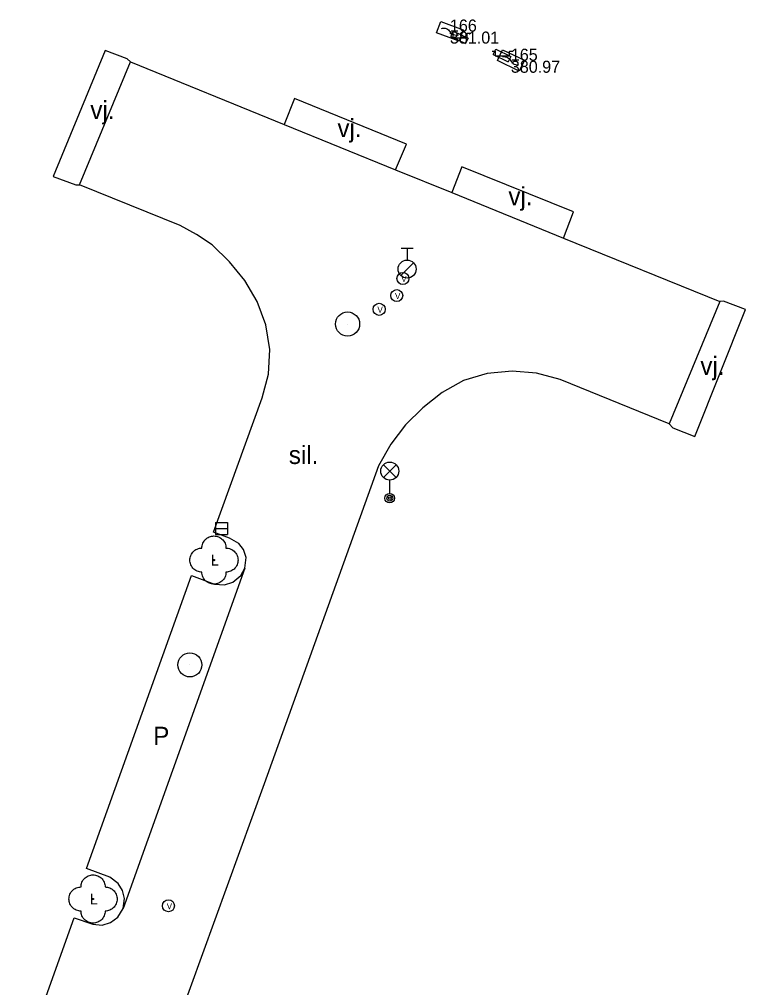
# Model space of a CAD drawing. Extents: x -836568 to -836015, y -1070547 to -1070212.
# Drawn here: x -836294.58 to -836264.42, y -1070423.41 to -1070383.21 of the extents above; entities that cross this region are included whole.
import ezdxf

# ---------------------------------------------------------------- set-up
doc = ezdxf.new("R2010")
doc.units = 0
for name, color, linetype in [('BodPole_mer', 7, 'Continuous'), ('BodPole_popis', 7, 'Continuous'), ('Doprava_hranice', 7, 'Continuous'), ('Doprava_kody', 7, 'Continuous'), ('PovrZnIS_body', 7, 'Continuous'), ('PovrZnIS_hranice', 7, 'Continuous'), ('PovrZnIS_kody', 7, 'Continuous'), ('Zelen_body', 7, 'Continuous')]:
    doc.layers.add(name, color=color, linetype=linetype)

msp = doc.modelspace()

# ---------------------------------------------------------------- linework, layer by layer
at = {"layer": 'BodPole_mer'}
for p, q in [((-836276.7, -1070383.72), (-836276.7, -1070383.72)), ((-836276.66, -1070383.93), (-836276.66, -1070383.93)), ((-836276.66, -1070383.93), (-836276.66, -1070383.93)), ((-836276.55, -1070383.7), (-836276.55, -1070383.7)), ((-836276.55, -1070383.7), (-836276.55, -1070383.7)), ((-836275.94, -1070383.99), (-836275.94, -1070383.99)), ((-836275.94, -1070383.99), (-836275.94, -1070383.99)), ((-836291.02, -1070384.5), (-836291.02, -1070384.5)), ((-836276.05, -1070384.22), (-836276.05, -1070384.22)), ((-836276.05, -1070384.22), (-836276.05, -1070384.22)), ((-836274.79, -1070384.45), (-836274.79, -1070384.45)), ((-836274.79, -1070384.45), (-836274.79, -1070384.45)), ((-836290.1, -1070384.85), (-836290.1, -1070384.85)), ((-836274.9, -1070384.67), (-836274.9, -1070384.67)), ((-836274.9, -1070384.67), (-836274.9, -1070384.67)), ((-836274.17, -1070384.76), (-836274.17, -1070384.76)), ((-836274.17, -1070384.76), (-836274.17, -1070384.76)), ((-836289.97, -1070384.98), (-836289.97, -1070384.98)), ((-836274.28, -1070384.98), (-836274.28, -1070384.98)), ((-836274.28, -1070384.98), (-836274.28, -1070384.98)), ((-836274.17, -1070384.93), (-836274.17, -1070384.93)), ((-836283.16, -1070386.5), (-836283.16, -1070386.5)), ((-836283.58, -1070387.58), (-836283.58, -1070387.58)), ((-836278.5, -1070388.39), (-836278.5, -1070388.39)), ((-836278.96, -1070389.46), (-836278.96, -1070389.46)), ((-836276.2, -1070389.34), (-836276.2, -1070389.34)), ((-836293.17, -1070389.73), (-836293.17, -1070389.73)), ((-836292.23, -1070390.08), (-836292.23, -1070390.08)), ((-836292.08, -1070390.08), (-836292.08, -1070390.08)), ((-836276.62, -1070390.4), (-836276.62, -1070390.4)), ((-836271.57, -1070391.2), (-836271.57, -1070391.2)), ((-836287.9, -1070391.77), (-836287.9, -1070391.77)), ((-836287.23, -1070392.15), (-836287.23, -1070392.15)), ((-836271.98, -1070392.3), (-836271.98, -1070392.3)), ((-836286.58, -1070392.57), (-836286.58, -1070392.57)), ((-836285.86, -1070393.28), (-836285.86, -1070393.28)), ((-836278.48, -1070393.58), (-836278.48, -1070393.58)), ((-836285.22, -1070394.06), (-836285.22, -1070394.06)), ((-836278.65, -1070393.97), (-836278.65, -1070393.97)), ((-836284.71, -1070394.93), (-836284.71, -1070394.93)), ((-836278.91, -1070394.68), (-836278.91, -1070394.68)), ((-836265.49, -1070394.92), (-836265.49, -1070394.92)), ((-836265.34, -1070394.91), (-836265.34, -1070394.91)), ((-836279.64, -1070395.25), (-836279.64, -1070395.25)), ((-836264.42, -1070395.26), (-836264.42, -1070395.26)), ((-836284.35, -1070395.9), (-836284.35, -1070395.9)), ((-836280.95, -1070395.86), (-836280.95, -1070395.86)), ((-836284.18, -1070396.92), (-836284.18, -1070396.92)), ((-836284.24, -1070397.94), (-836284.24, -1070397.94)), ((-836275.16, -1070397.91), (-836275.16, -1070397.91)), ((-836274.12, -1070397.82), (-836274.12, -1070397.82)), ((-836273.11, -1070397.9), (-836273.11, -1070397.9)), ((-836276.14, -1070398.21), (-836276.14, -1070398.21)), ((-836272.12, -1070398.17), (-836272.12, -1070398.17)), ((-836284.5, -1070398.92), (-836284.5, -1070398.92)), ((-836277.02, -1070398.7), (-836277.02, -1070398.7)), ((-836277.82, -1070399.34), (-836277.82, -1070399.34)), ((-836278.55, -1070400.05), (-836278.55, -1070400.05)), ((-836267.59, -1070400.01), (-836267.59, -1070400.01)), ((-836267.44, -1070400.17), (-836267.44, -1070400.17)), ((-836266.53, -1070400.53), (-836266.53, -1070400.53)), ((-836279.16, -1070400.85), (-836279.16, -1070400.85)), ((-836279.66, -1070401.75), (-836279.66, -1070401.75)), ((-836279.2, -1070403.09), (-836279.2, -1070403.09)), ((-836286.52, -1070404.5), (-836286.52, -1070404.5)), ((-836286.19, -1070404.35), (-836286.19, -1070404.35)), ((-836285.85, -1070404.75), (-836285.85, -1070404.75)), ((-836285.46, -1070404.97), (-836285.46, -1070404.97)), ((-836285.27, -1070405.22), (-836285.27, -1070405.22)), ((-836286.5, -1070405.66), (-836286.5, -1070405.66)), ((-836285.16, -1070405.55), (-836285.16, -1070405.55)), ((-836285.22, -1070406), (-836285.22, -1070406)), ((-836287.43, -1070406.3), (-836287.43, -1070406.3)), ((-836285.71, -1070406.58), (-836285.71, -1070406.58)), ((-836285.38, -1070406.3), (-836285.38, -1070406.3)), ((-836286.47, -1070406.66), (-836286.47, -1070406.66)), ((-836286.06, -1070406.69), (-836286.06, -1070406.69)), ((-836287.5, -1070410.01), (-836287.5, -1070410.01)), ((-836284.42, -1070414.95), (-836284.42, -1070414.95)), ((-836291.79, -1070418.47), (-836291.79, -1070418.47)), ((-836290.82, -1070418.83), (-836290.82, -1070418.83)), ((-836290.47, -1070419.09), (-836290.47, -1070419.09)), ((-836290.3, -1070419.37), (-836290.3, -1070419.37)), ((-836291.52, -1070419.73), (-836291.52, -1070419.73)), ((-836290.21, -1070419.71), (-836290.21, -1070419.71)), ((-836290.27, -1070420.13), (-836290.27, -1070420.13)), ((-836288.39, -1070420.01), (-836288.39, -1070420.01)), ((-836292.3, -1070420.51), (-836292.3, -1070420.51)), ((-836290.49, -1070420.48), (-836290.49, -1070420.48)), ((-836291.53, -1070420.77), (-836291.53, -1070420.77)), ((-836291.14, -1070420.81), (-836291.14, -1070420.81)), ((-836290.8, -1070420.71), (-836290.8, -1070420.71))]:
    msp.add_line(p, q, dxfattribs=at)
at = {"layer": 'Doprava_hranice'}
msp.add_line((-836285.22, -1070406), (-836290.27, -1070420.13), dxfattribs=at)
for points in [[(-836289.97, -1070384.98), (-836290.1, -1070384.85), (-836291.02, -1070384.5), (-836293.17, -1070389.73), (-836292.23, -1070390.08), (-836292.08, -1070390.08)], [(-836294.58, -1070426.87), (-836292.3, -1070420.51), (-836291.53, -1070420.77), (-836291.14, -1070420.81), (-836290.8, -1070420.71), (-836290.49, -1070420.48), (-836290.27, -1070420.13), (-836290.21, -1070419.71), (-836290.3, -1070419.37), (-836290.47, -1070419.09), (-836290.82, -1070418.83), (-836291.79, -1070418.47), (-836287.43, -1070406.3), (-836286.47, -1070406.66), (-836286.06, -1070406.69), (-836285.71, -1070406.58), (-836285.38, -1070406.3), (-836285.22, -1070406), (-836285.16, -1070405.55), (-836285.27, -1070405.22), (-836285.46, -1070404.97), (-836285.85, -1070404.75), (-836286.52, -1070404.5), (-836284.5, -1070398.92), (-836284.24, -1070397.94), (-836284.18, -1070396.92), (-836284.35, -1070395.9), (-836284.71, -1070394.93), (-836285.22, -1070394.06), (-836285.86, -1070393.28), (-836286.58, -1070392.57), (-836287.23, -1070392.15), (-836287.9, -1070391.77), (-836292.08, -1070390.08), (-836289.97, -1070384.98), (-836283.58, -1070387.58), (-836278.96, -1070389.46), (-836276.62, -1070390.4), (-836271.98, -1070392.3), (-836265.49, -1070394.92), (-836267.59, -1070400.01), (-836272.12, -1070398.17), (-836273.11, -1070397.9), (-836274.12, -1070397.82), (-836275.16, -1070397.91), (-836276.14, -1070398.21), (-836277.02, -1070398.7), (-836277.82, -1070399.34), (-836278.55, -1070400.05), (-836279.16, -1070400.85), (-836279.66, -1070401.75), (-836284.42, -1070414.95), (-836289.53, -1070429.07)], [(-836278.96, -1070389.46), (-836278.5, -1070388.39), (-836283.16, -1070386.5), (-836283.58, -1070387.58)], [(-836271.98, -1070392.3), (-836271.57, -1070391.2), (-836276.2, -1070389.34), (-836276.62, -1070390.4)], [(-836267.59, -1070400.01), (-836267.44, -1070400.17), (-836266.53, -1070400.53), (-836264.42, -1070395.26), (-836265.34, -1070394.91), (-836265.49, -1070394.92)]]:
    msp.add_lwpolyline(points, dxfattribs=at)
at = {"layer": 'PovrZnIS_body'}
for p, q in [((-836277.256, -1070383.765), (-836277.08, -1070383.297)), ((-836277.08, -1070383.297), (-836276.144, -1070383.649)), ((-836276.144, -1070383.649), (-836276.321, -1070384.117)), ((-836276.321, -1070384.117), (-836277.256, -1070383.765)), ((-836274.728, -1070384.925), (-836274.511, -1070384.475)), ((-836274.511, -1070384.475), (-836273.61, -1070384.909)), ((-836273.828, -1070385.36), (-836274.728, -1070384.925)), ((-836273.61, -1070384.909), (-836273.828, -1070385.36)), ((-836278.73, -1070392.705), (-836278.23, -1070392.705)), ((-836278.48, -1070392.705), (-836278.48, -1070393.205)), ((-836278.215, -1070393.315), (-836278.745, -1070393.845)), ((-836279.465, -1070402.23), (-836278.935, -1070401.7)), ((-836279.465, -1070401.7), (-836278.935, -1070402.23)), ((-836279.2, -1070402.89), (-836279.2, -1070402.34)), ((-836286.44, -1070404.1), (-836285.94, -1070404.1)), ((-836286.44, -1070404.1), (-836286.44, -1070404.6)), ((-836285.94, -1070404.1), (-836285.94, -1070404.6)), ((-836286.44, -1070404.35), (-836285.94, -1070404.35)), ((-836286.44, -1070404.6), (-836285.94, -1070404.6))]:
    msp.add_line(p, q, dxfattribs=at)
for points in [[(-836277.052, -1070383.587), (-836277.005, -1070383.577), (-836276.955, -1070383.575), (-836276.904, -1070383.581), (-836276.854, -1070383.595), (-836276.807, -1070383.617), (-836276.765, -1070383.647), (-836276.729, -1070383.682), (-836276.7, -1070383.72)], [(-836276.7, -1070383.72), (-836276.671, -1070383.758), (-836276.635, -1070383.793), (-836276.593, -1070383.822), (-836276.547, -1070383.845), (-836276.497, -1070383.859), (-836276.446, -1070383.864), (-836276.396, -1070383.862), (-836276.349, -1070383.852)], [(-836274.509, -1070384.766), (-836274.461, -1070384.761), (-836274.411, -1070384.763), (-836274.361, -1070384.773), (-836274.312, -1070384.792), (-836274.267, -1070384.818), (-836274.228, -1070384.851), (-836274.195, -1070384.889), (-836274.17, -1070384.93)], [(-836274.17, -1070384.93), (-836274.145, -1070384.971), (-836274.112, -1070385.009), (-836274.073, -1070385.041), (-836274.028, -1070385.068), (-836273.98, -1070385.086), (-836273.93, -1070385.097), (-836273.88, -1070385.099), (-836273.832, -1070385.093)]]:
    msp.add_lwpolyline(points, dxfattribs=at)
for centre, radius in [((-836278.48, -1070393.58), 0.375), ((-836278.65, -1070393.97), 0.25), ((-836278.91, -1070394.68), 0.25), ((-836279.64, -1070395.25), 0.25), ((-836280.95, -1070395.86), 0.5), ((-836287.5, -1070410.01), 0.5), ((-836288.39, -1070420.01), 0.25)]:
    msp.add_circle(centre, radius, dxfattribs=at)
for centre, major_axis in [((-836279.2, -1070401.965), (0.375, 0)), ((-836279.2, -1070403.09), (0.2, 0)), ((-836279.196, -1070403.09), (0.125, 0)), ((-836279.196, -1070403.09), (0.05, 0))]:
    msp.add_ellipse(centre, major_axis=major_axis, ratio=0.999998, dxfattribs=at)
at = {"layer": 'PovrZnIS_hranice'}
for p, q in [((-836276.66, -1070383.93), (-836276.05, -1070384.22)), ((-836276.66, -1070383.93), (-836276.05, -1070384.22)), ((-836274.9, -1070384.67), (-836274.28, -1070384.98)), ((-836274.9, -1070384.67), (-836274.28, -1070384.98))]:
    msp.add_line(p, q, dxfattribs=at)
for points in [[(-836276.66, -1070383.93), (-836276.55, -1070383.7), (-836275.94, -1070383.99), (-836276.05, -1070384.22)], [(-836276.66, -1070383.93), (-836276.55, -1070383.7), (-836275.94, -1070383.99), (-836276.05, -1070384.22)], [(-836274.9, -1070384.67), (-836274.79, -1070384.45), (-836274.17, -1070384.76), (-836274.28, -1070384.98)], [(-836274.9, -1070384.67), (-836274.79, -1070384.45), (-836274.17, -1070384.76), (-836274.28, -1070384.98)]]:
    msp.add_lwpolyline(points, dxfattribs=at)
at = {"layer": 'PovrZnIS_kody'}
for p, q in [((-836276.701, -1070383.78), (-836276.58, -1070383.78)), ((-836276.701, -1070383.78), (-836276.58, -1070383.78)), ((-836276.58, -1070383.78), (-836276.58, -1070383.98)), ((-836276.58, -1070383.78), (-836276.58, -1070383.98)), ((-836276.58, -1070383.98), (-836275.98, -1070383.98)), ((-836276.58, -1070383.98), (-836275.98, -1070383.98)), ((-836275.98, -1070383.98), (-836275.98, -1070383.78)), ((-836275.98, -1070383.78), (-836275.846, -1070383.78)), ((-836275.98, -1070383.98), (-836275.98, -1070383.78)), ((-836275.98, -1070383.78), (-836275.846, -1070383.78)), ((-836274.941, -1070384.53), (-836274.82, -1070384.53)), ((-836274.941, -1070384.53), (-836274.82, -1070384.53)), ((-836274.82, -1070384.53), (-836274.82, -1070384.73)), ((-836274.82, -1070384.53), (-836274.82, -1070384.73)), ((-836274.82, -1070384.73), (-836274.22, -1070384.73)), ((-836274.82, -1070384.73), (-836274.22, -1070384.73)), ((-836274.22, -1070384.73), (-836274.22, -1070384.53)), ((-836274.22, -1070384.53), (-836274.086, -1070384.53)), ((-836274.22, -1070384.73), (-836274.22, -1070384.53)), ((-836274.22, -1070384.53), (-836274.086, -1070384.53))]:
    msp.add_line(p, q, dxfattribs=at)
at = {"layer": 'Zelen_body'}
for p, q in [((-836286.5, -1070405.66), (-836286.5, -1070405.66)), ((-836291.52, -1070419.73), (-836291.52, -1070419.73))]:
    msp.add_line(p, q, dxfattribs=at)
for points in [[(-836287, -1070405.16), (-836286.998, -1070405.112), (-836286.99, -1070405.063), (-836286.978, -1070405.013), (-836286.96, -1070404.964), (-836286.936, -1070404.915), (-836286.907, -1070404.869), (-836286.873, -1070404.826), (-836286.834, -1070404.787), (-836286.791, -1070404.753), (-836286.745, -1070404.724), (-836286.696, -1070404.7), (-836286.647, -1070404.682), (-836286.597, -1070404.67), (-836286.548, -1070404.662), (-836286.5, -1070404.66), (-836286.452, -1070404.662), (-836286.403, -1070404.67), (-836286.353, -1070404.682), (-836286.304, -1070404.7), (-836286.255, -1070404.724), (-836286.209, -1070404.753), (-836286.166, -1070404.787), (-836286.127, -1070404.826), (-836286.093, -1070404.869), (-836286.064, -1070404.915), (-836286.04, -1070404.964), (-836286.022, -1070405.013), (-836286.01, -1070405.063), (-836286.002, -1070405.112), (-836286, -1070405.16)], [(-836287, -1070406.16), (-836287.048, -1070406.158), (-836287.097, -1070406.15), (-836287.147, -1070406.138), (-836287.196, -1070406.12), (-836287.245, -1070406.096), (-836287.291, -1070406.067), (-836287.334, -1070406.033), (-836287.373, -1070405.994), (-836287.407, -1070405.951), (-836287.436, -1070405.905), (-836287.46, -1070405.856), (-836287.478, -1070405.807), (-836287.49, -1070405.757), (-836287.498, -1070405.708), (-836287.5, -1070405.66), (-836287.498, -1070405.612), (-836287.49, -1070405.563), (-836287.478, -1070405.513), (-836287.46, -1070405.464), (-836287.436, -1070405.415), (-836287.407, -1070405.369), (-836287.373, -1070405.326), (-836287.334, -1070405.287), (-836287.291, -1070405.253), (-836287.245, -1070405.224), (-836287.196, -1070405.2), (-836287.147, -1070405.182), (-836287.097, -1070405.17), (-836287.048, -1070405.162), (-836287, -1070405.16)], [(-836286, -1070405.16), (-836285.952, -1070405.162), (-836285.903, -1070405.17), (-836285.853, -1070405.182), (-836285.804, -1070405.2), (-836285.755, -1070405.224), (-836285.709, -1070405.253), (-836285.666, -1070405.287), (-836285.627, -1070405.326), (-836285.593, -1070405.369), (-836285.564, -1070405.415), (-836285.54, -1070405.464), (-836285.522, -1070405.513), (-836285.51, -1070405.563), (-836285.502, -1070405.612), (-836285.5, -1070405.66), (-836285.502, -1070405.708), (-836285.51, -1070405.757), (-836285.522, -1070405.807), (-836285.54, -1070405.856), (-836285.564, -1070405.905), (-836285.593, -1070405.951), (-836285.627, -1070405.994), (-836285.666, -1070406.033), (-836285.709, -1070406.067), (-836285.755, -1070406.096), (-836285.804, -1070406.12), (-836285.853, -1070406.138), (-836285.903, -1070406.15), (-836285.952, -1070406.158), (-836286, -1070406.16)], [(-836286, -1070406.16), (-836286.002, -1070406.208), (-836286.01, -1070406.257), (-836286.022, -1070406.307), (-836286.04, -1070406.356), (-836286.064, -1070406.405), (-836286.093, -1070406.451), (-836286.127, -1070406.494), (-836286.166, -1070406.533), (-836286.209, -1070406.567), (-836286.255, -1070406.596), (-836286.304, -1070406.62), (-836286.353, -1070406.638), (-836286.403, -1070406.65), (-836286.452, -1070406.658), (-836286.5, -1070406.66), (-836286.548, -1070406.658), (-836286.597, -1070406.65), (-836286.647, -1070406.638), (-836286.696, -1070406.62), (-836286.745, -1070406.596), (-836286.791, -1070406.567), (-836286.834, -1070406.533), (-836286.873, -1070406.494), (-836286.907, -1070406.451), (-836286.936, -1070406.405), (-836286.96, -1070406.356), (-836286.978, -1070406.307), (-836286.99, -1070406.257), (-836286.998, -1070406.208), (-836287, -1070406.16)], [(-836292.02, -1070419.23), (-836292.018, -1070419.182), (-836292.01, -1070419.133), (-836291.998, -1070419.083), (-836291.98, -1070419.034), (-836291.956, -1070418.985), (-836291.927, -1070418.939), (-836291.893, -1070418.896), (-836291.854, -1070418.857), (-836291.811, -1070418.823), (-836291.765, -1070418.794), (-836291.716, -1070418.77), (-836291.667, -1070418.752), (-836291.617, -1070418.74), (-836291.568, -1070418.732), (-836291.52, -1070418.73), (-836291.472, -1070418.732), (-836291.423, -1070418.74), (-836291.373, -1070418.752), (-836291.324, -1070418.77), (-836291.275, -1070418.794), (-836291.229, -1070418.823), (-836291.186, -1070418.857), (-836291.147, -1070418.896), (-836291.113, -1070418.939), (-836291.084, -1070418.985), (-836291.06, -1070419.034), (-836291.042, -1070419.083), (-836291.03, -1070419.133), (-836291.022, -1070419.182), (-836291.02, -1070419.23)], [(-836292.02, -1070420.23), (-836292.068, -1070420.228), (-836292.117, -1070420.22), (-836292.167, -1070420.208), (-836292.216, -1070420.19), (-836292.265, -1070420.166), (-836292.311, -1070420.137), (-836292.354, -1070420.103), (-836292.393, -1070420.064), (-836292.427, -1070420.021), (-836292.456, -1070419.975), (-836292.48, -1070419.926), (-836292.498, -1070419.877), (-836292.51, -1070419.827), (-836292.518, -1070419.778), (-836292.52, -1070419.73), (-836292.518, -1070419.682), (-836292.51, -1070419.633), (-836292.498, -1070419.583), (-836292.48, -1070419.534), (-836292.456, -1070419.485), (-836292.427, -1070419.439), (-836292.393, -1070419.396), (-836292.354, -1070419.357), (-836292.311, -1070419.323), (-836292.265, -1070419.294), (-836292.216, -1070419.27), (-836292.167, -1070419.252), (-836292.117, -1070419.24), (-836292.068, -1070419.232), (-836292.02, -1070419.23)], [(-836291.02, -1070419.23), (-836290.972, -1070419.232), (-836290.923, -1070419.24), (-836290.873, -1070419.252), (-836290.824, -1070419.27), (-836290.775, -1070419.294), (-836290.729, -1070419.323), (-836290.686, -1070419.357), (-836290.647, -1070419.396), (-836290.613, -1070419.439), (-836290.584, -1070419.485), (-836290.56, -1070419.534), (-836290.542, -1070419.583), (-836290.53, -1070419.633), (-836290.522, -1070419.682), (-836290.52, -1070419.73), (-836290.522, -1070419.778), (-836290.53, -1070419.827), (-836290.542, -1070419.877), (-836290.56, -1070419.926), (-836290.584, -1070419.975), (-836290.613, -1070420.021), (-836290.647, -1070420.064), (-836290.686, -1070420.103), (-836290.729, -1070420.137), (-836290.775, -1070420.166), (-836290.824, -1070420.19), (-836290.873, -1070420.208), (-836290.923, -1070420.22), (-836290.972, -1070420.228), (-836291.02, -1070420.23)], [(-836291.02, -1070420.23), (-836291.022, -1070420.278), (-836291.03, -1070420.327), (-836291.042, -1070420.377), (-836291.06, -1070420.426), (-836291.084, -1070420.475), (-836291.113, -1070420.521), (-836291.147, -1070420.564), (-836291.186, -1070420.603), (-836291.229, -1070420.637), (-836291.275, -1070420.666), (-836291.324, -1070420.69), (-836291.373, -1070420.708), (-836291.423, -1070420.72), (-836291.472, -1070420.728), (-836291.52, -1070420.73), (-836291.568, -1070420.728), (-836291.617, -1070420.72), (-836291.667, -1070420.708), (-836291.716, -1070420.69), (-836291.765, -1070420.666), (-836291.811, -1070420.637), (-836291.854, -1070420.603), (-836291.893, -1070420.564), (-836291.927, -1070420.521), (-836291.956, -1070420.475), (-836291.98, -1070420.426), (-836291.998, -1070420.377), (-836292.01, -1070420.327), (-836292.018, -1070420.278), (-836292.02, -1070420.23)]]:
    msp.add_lwpolyline(points, dxfattribs=at)
for centre in [(-836286.5, -1070405.66), (-836291.52, -1070419.73)]:
    msp.add_ellipse(centre, major_axis=(0.025, 0), ratio=0.999997, dxfattribs=at)

# ---------------------------------------------------------------- texts
at = {"layer": 'BodPole_popis'}
for s, p in [('166', (-836276.7, -1070383.72)), ('381.01', (-836276.7, -1070384.22)), ('165', (-836274.17, -1070384.93)), ('380.97', (-836274.17, -1070385.43))]:
    msp.add_text(s, height=0.5, dxfattribs=at).set_placement(p)
at = {"layer": 'Doprava_kody'}
for s, p in [('vj.', (-836291.63, -1070387.35)), ('vj.', (-836281.37, -1070388.1)), ('vj.', (-836274.27, -1070390.93)), ('vj.', (-836266.3, -1070397.97)), ('sil.', (-836283.39, -1070401.67)), ('P', (-836289.02, -1070413.33))]:
    msp.add_text(s, height=0.75, dxfattribs=at).set_placement(p)
at = {"layer": 'PovrZnIS_body'}
for p in [(-836278.721, -1070394.113), (-836278.981, -1070394.823), (-836279.711, -1070395.393), (-836288.461, -1070420.153)]:
    msp.add_text('V', height=0.25, dxfattribs=at).set_placement(p)
at = {"layer": 'Zelen_body'}
for p in [(-836286.631, -1070405.885), (-836291.651, -1070419.955)]:
    msp.add_text('L', height=0.45, dxfattribs=at).set_placement(p)

doc.saveas('drawing.dxf')
